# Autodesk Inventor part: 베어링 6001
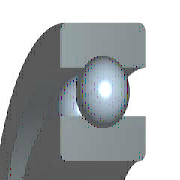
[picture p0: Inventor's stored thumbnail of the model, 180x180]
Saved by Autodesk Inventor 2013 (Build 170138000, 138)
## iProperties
Created: 2012-02
Part Number: 베어링 6001
Material: 강철, 연강
Description: 깊은 그루브 볼 베어링
Document SubType Name: Modeling
Standard: KS B 2023
Designer: mduedu
Standards Organization: KS
Language: ko-KR
Size Designation: 6001 - 12 x 28 x 8
Categories: <MemberInstance><Categories><Category DisplayName="샤프트 부품" InternalName="7f7aeb1f-a693-4053-b835-cee3144e0d98" Mnemonic="SHFT"><Category DisplayName="베어링" Inter
Density: 7.86 g/cm^3
Mass: 21.4855 g
Surface Area: 31.1809 cm^2
Volume: 2.73352 cm^3
IsCustomPart: 1
Author: mduedu
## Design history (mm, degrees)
sketch "스케치" dims "d0" = 4.16 (= -0.26 x WD + 0.26 x BD)
  geometry: L1 (1.92, 10)-(6.08, 10); L2 (4, 10)-(4, 7.92); L3 (4, 10)-(4, 12.08); L4 (2.454, 8.608)-(0, 8.608); L5 (0, 6)-(8, 6); L6 (2.454, 11.392)-(0, 11.392); L7 (0, 14)-(8, 14); L8 (8, 6)-(8, 8.608); L9 (5.546, 8.608)-(8, 8.608); L10 (5.546, 11.392)-(8, 11.392); L11 (8, 14)-(8, 11.392); L12 (-1.4, 0)-(8.4, 0) reference; L13 (0, -0.3)-(0, 5.3) reference
  constraints: 22 end point, 4 point on line, 2 collinear, 2 perpendicular, 2 symmetric about line, 1 midpoint, 1 parallel, 14 other
  dimensions: "d9" = 12 diameter of L5 L12 (= WD); "d11" = 28 diameter of L7 L12 (= BD); "d12" = 8 distance between parallel lines of L8 L13 (= KB); "d13" = 17.216 diameter of L9 L12 (= 0.326 x BD + 0.674 x WD)
revolve "본체" stored, may be unused: angle "d6" = 90 deg
revolve "볼" stored, may be unused: angle "d7" = 90 deg
pattern_circular "IDS_ARRAYBALL[SIMPL:T]" dims angle "d3" = 360 deg
body "Solid1"
fillet "모깎기1" dims "d1" = 0.3 (= KRS)
other parameters: "WD" = 12 [user parameter; used in 5 equation terms], "BD" = 28 [user parameter; used in 5 equation terms], "KB" = 8 [user parameter; used in 1 equation term], "KRS" = 0.3 [user parameter; used in 1 equation term], "d4" = 0, "d5" = 0, "d8" = 0, "d14" = 0, "d15" = 0, "BBA" = 0 [user parameter], "BC0" = 2360000 [user parameter], "BC" = 5070000 [user parameter], "BR" = 14 (= 0.5 x BD) [user parameter], "WR" = 6 (= 0.5 x WD) [user parameter]
